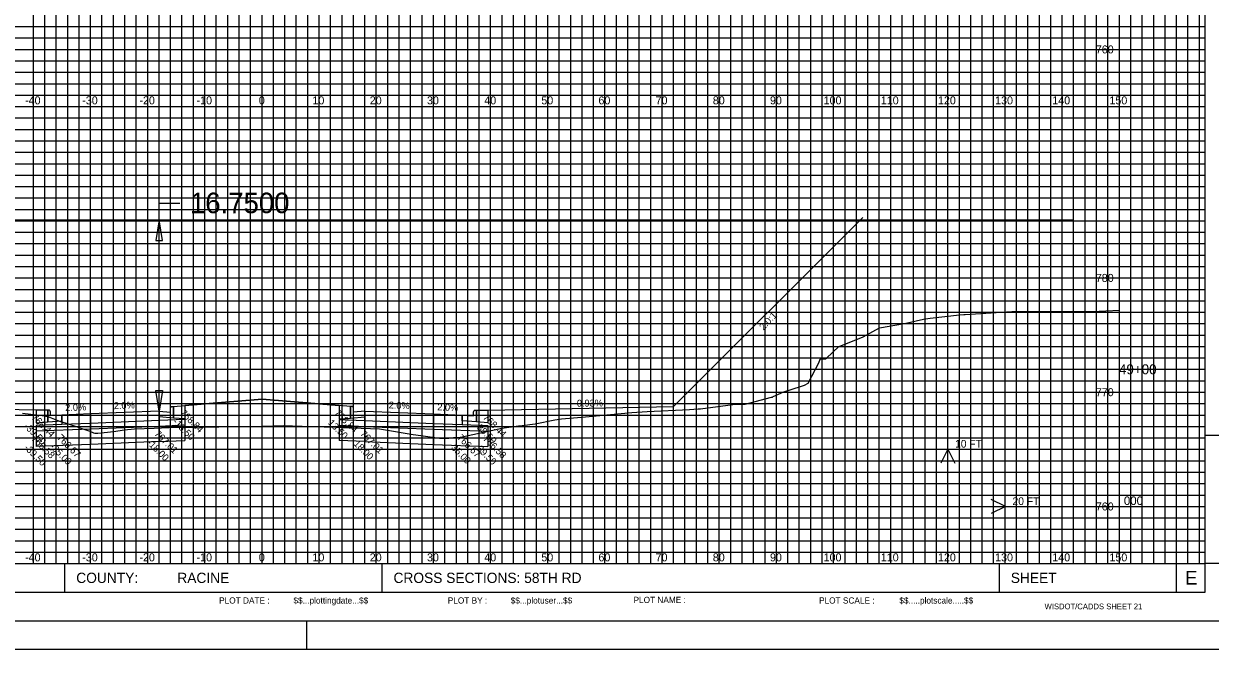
# Model space of a CAD drawing. Extents: x 578243 to 601557, y 174899 to 175559.
# Drawn here: x 600658.2 to 600865.7, y 175338.8 to 175448.3 of the extents above; entities that cross this region are included whole.
import ezdxf

# ---------------------------------------------------------------- set-up
doc = ezdxf.new("R2010")
doc.units = 0
for name, color, linetype in [('E_PROF_Grid', 7, 'Continuous'), ('E_PROF_GridMin', 7, 'Continuous'), ('P_CRDR_Label', 7, 'Continuous'), ('P_CRDR_Link', 7, 'Continuous'), ('P_E_XS_Ground', 7, 'Continuous'), ('P_RW_SlopeIntercepts', 7, 'Continuous'), ('P_XS_Text', 7, 'Continuous'), ('PLT_Sheet_Border', 7, 'Continuous'), ('PLT_Sheet_Info', 7, 'Continuous')]:
    doc.layers.add(name, color=color, linetype=linetype)

msp = doc.modelspace()

# ---------------------------------------------------------------- linework, layer by layer
at = {"layer": 'E_PROF_Grid'}
for p, q in [((600659.84, 175353.8), (600659.84, 175548.8)), ((600669.84, 175353.8), (600669.84, 175548.8)), ((600679.84, 175353.8), (600679.84, 175548.8)), ((600689.84, 175353.8), (600689.84, 175548.8)), ((600699.84, 175353.8), (600699.84, 175548.8)), ((600709.84, 175353.8), (600709.84, 175548.8)), ((600719.84, 175353.8), (600719.84, 175548.8)), ((600729.84, 175353.8), (600729.84, 175548.8)), ((600739.84, 175353.8), (600739.84, 175548.8)), ((600749.84, 175353.8), (600749.84, 175548.8)), ((600759.84, 175353.8), (600759.84, 175548.8)), ((600769.84, 175353.8), (600769.84, 175548.8)), ((600779.84, 175353.8), (600779.84, 175548.8)), ((600789.84, 175353.8), (600789.84, 175548.8)), ((600799.84, 175353.8), (600799.84, 175548.8)), ((600809.84, 175353.8), (600809.84, 175548.8)), ((600819.84, 175353.8), (600819.84, 175548.8)), ((600829.84, 175353.8), (600829.84, 175548.8)), ((600839.84, 175353.8), (600839.84, 175548.8)), ((600849.84, 175353.8), (600849.84, 175548.8)), ((600859.84, 175353.8), (600859.84, 175548.8)), ((600549.84, 175443.8), (600864.84, 175443.8)), ((600549.84, 175433.8), (600864.84, 175433.8)), ((600549.84, 175423.8), (600864.84, 175423.8)), ((600549.84, 175413.8), (600864.84, 175413.8)), ((600549.84, 175403.8), (600864.84, 175403.8)), ((600549.84, 175393.8), (600864.84, 175393.8)), ((600549.84, 175383.8), (600864.84, 175383.8)), ((600549.84, 175373.8), (600864.84, 175373.8)), ((600549.84, 175363.8), (600864.84, 175363.8))]:
    msp.add_line(p, q, dxfattribs=at)
at = {"layer": 'E_PROF_GridMin'}
for p, q in [((600661.84, 175353.8), (600661.84, 175548.8)), ((600663.84, 175353.8), (600663.84, 175548.8)), ((600665.84, 175353.8), (600665.84, 175548.8)), ((600667.84, 175353.8), (600667.84, 175548.8)), ((600671.84, 175353.8), (600671.84, 175548.8)), ((600673.84, 175353.8), (600673.84, 175548.8)), ((600675.84, 175353.8), (600675.84, 175548.8)), ((600677.84, 175353.8), (600677.84, 175548.8)), ((600681.84, 175353.8), (600681.84, 175548.8)), ((600683.84, 175353.8), (600683.84, 175548.8)), ((600685.84, 175353.8), (600685.84, 175548.8)), ((600687.84, 175353.8), (600687.84, 175548.8)), ((600691.84, 175353.8), (600691.84, 175548.8)), ((600693.84, 175353.8), (600693.84, 175548.8)), ((600695.84, 175353.8), (600695.84, 175548.8)), ((600697.84, 175353.8), (600697.84, 175548.8)), ((600701.84, 175353.8), (600701.84, 175548.8)), ((600703.84, 175353.8), (600703.84, 175548.8)), ((600705.84, 175353.8), (600705.84, 175548.8)), ((600707.84, 175353.8), (600707.84, 175548.8)), ((600711.84, 175353.8), (600711.84, 175548.8)), ((600713.84, 175353.8), (600713.84, 175548.8)), ((600715.84, 175353.8), (600715.84, 175548.8)), ((600717.84, 175353.8), (600717.84, 175548.8)), ((600721.84, 175353.8), (600721.84, 175548.8)), ((600723.84, 175353.8), (600723.84, 175548.8)), ((600725.84, 175353.8), (600725.84, 175548.8)), ((600727.84, 175353.8), (600727.84, 175548.8)), ((600731.84, 175353.8), (600731.84, 175548.8)), ((600733.84, 175353.8), (600733.84, 175548.8)), ((600735.84, 175353.8), (600735.84, 175548.8)), ((600737.84, 175353.8), (600737.84, 175548.8)), ((600741.84, 175353.8), (600741.84, 175548.8)), ((600743.84, 175353.8), (600743.84, 175548.8)), ((600745.84, 175353.8), (600745.84, 175548.8)), ((600747.84, 175353.8), (600747.84, 175548.8)), ((600751.84, 175353.8), (600751.84, 175548.8)), ((600753.84, 175353.8), (600753.84, 175548.8)), ((600755.84, 175353.8), (600755.84, 175548.8)), ((600757.84, 175353.8), (600757.84, 175548.8)), ((600761.84, 175353.8), (600761.84, 175548.8)), ((600763.84, 175353.8), (600763.84, 175548.8)), ((600765.84, 175353.8), (600765.84, 175548.8)), ((600767.84, 175353.8), (600767.84, 175548.8)), ((600771.84, 175353.8), (600771.84, 175548.8)), ((600773.84, 175353.8), (600773.84, 175548.8)), ((600775.84, 175353.8), (600775.84, 175548.8)), ((600777.84, 175353.8), (600777.84, 175548.8)), ((600781.84, 175353.8), (600781.84, 175548.8)), ((600783.84, 175353.8), (600783.84, 175548.8)), ((600785.84, 175353.8), (600785.84, 175548.8)), ((600787.84, 175353.8), (600787.84, 175548.8)), ((600791.84, 175353.8), (600791.84, 175548.8)), ((600793.84, 175353.8), (600793.84, 175548.8)), ((600795.84, 175353.8), (600795.84, 175548.8)), ((600797.84, 175353.8), (600797.84, 175548.8)), ((600801.84, 175353.8), (600801.84, 175548.8)), ((600803.84, 175353.8), (600803.84, 175548.8)), ((600805.84, 175353.8), (600805.84, 175548.8)), ((600807.84, 175353.8), (600807.84, 175548.8)), ((600811.84, 175353.8), (600811.84, 175548.8)), ((600813.84, 175353.8), (600813.84, 175548.8)), ((600815.84, 175353.8), (600815.84, 175548.8)), ((600817.84, 175353.8), (600817.84, 175548.8)), ((600821.84, 175353.8), (600821.84, 175548.8)), ((600823.84, 175353.8), (600823.84, 175548.8)), ((600825.84, 175353.8), (600825.84, 175548.8)), ((600827.84, 175353.8), (600827.84, 175548.8)), ((600831.84, 175353.8), (600831.84, 175548.8)), ((600833.84, 175353.8), (600833.84, 175548.8)), ((600835.84, 175353.8), (600835.84, 175548.8)), ((600837.84, 175353.8), (600837.84, 175548.8)), ((600841.84, 175353.8), (600841.84, 175548.8)), ((600843.84, 175353.8), (600843.84, 175548.8)), ((600845.84, 175353.8), (600845.84, 175548.8)), ((600847.84, 175353.8), (600847.84, 175548.8)), ((600851.84, 175353.8), (600851.84, 175548.8)), ((600853.84, 175353.8), (600853.84, 175548.8)), ((600855.84, 175353.8), (600855.84, 175548.8)), ((600857.84, 175353.8), (600857.84, 175548.8)), ((600861.84, 175353.8), (600861.84, 175548.8)), ((600863.84, 175353.8), (600863.84, 175548.8)), ((600549.84, 175447.8), (600864.84, 175447.8)), ((600549.84, 175445.8), (600864.84, 175445.8)), ((600549.84, 175441.8), (600864.84, 175441.8)), ((600549.84, 175439.8), (600864.84, 175439.8)), ((600549.84, 175437.8), (600864.84, 175437.8)), ((600549.84, 175435.8), (600864.84, 175435.8)), ((600549.84, 175431.8), (600864.84, 175431.8)), ((600549.84, 175429.8), (600864.84, 175429.8)), ((600549.84, 175427.8), (600864.84, 175427.8)), ((600549.84, 175425.8), (600864.84, 175425.8)), ((600549.84, 175421.8), (600864.84, 175421.8)), ((600549.84, 175419.8), (600864.84, 175419.8)), ((600549.84, 175417.8), (600864.84, 175417.8)), ((600549.84, 175415.8), (600864.84, 175415.8)), ((600549.84, 175411.8), (600864.84, 175411.8)), ((600549.84, 175409.8), (600864.84, 175409.8)), ((600549.84, 175407.8), (600864.84, 175407.8)), ((600549.84, 175405.8), (600864.84, 175405.8)), ((600549.84, 175401.8), (600864.84, 175401.8)), ((600549.84, 175399.8), (600864.84, 175399.8)), ((600549.84, 175397.8), (600864.84, 175397.8)), ((600549.84, 175395.8), (600864.84, 175395.8)), ((600549.84, 175391.8), (600864.84, 175391.8)), ((600549.84, 175389.8), (600864.84, 175389.8)), ((600549.84, 175387.8), (600864.84, 175387.8)), ((600549.84, 175385.8), (600864.84, 175385.8)), ((600549.84, 175381.8), (600864.84, 175381.8)), ((600549.84, 175379.8), (600864.84, 175379.8)), ((600549.84, 175377.8), (600864.84, 175377.8)), ((600549.84, 175375.8), (600864.84, 175375.8)), ((600549.84, 175371.8), (600864.84, 175371.8)), ((600549.84, 175369.8), (600864.84, 175369.8)), ((600549.84, 175367.8), (600864.84, 175367.8)), ((600549.84, 175365.8), (600864.84, 175365.8)), ((600549.84, 175361.8), (600864.84, 175361.8)), ((600549.84, 175359.8), (600864.84, 175359.8)), ((600549.84, 175357.8), (600864.84, 175357.8)), ((600549.84, 175355.8), (600864.84, 175355.8))]:
    msp.add_line(p, q, dxfattribs=at)
at = {"layer": 'P_CRDR_Link'}
msp.add_line((600804.95, 175414.4), (600771.84, 175381.28), dxfattribs=at)
for points in [[(600686.34, 175381.48), (600699.84, 175382.56)], [(600686.34, 175381.48), (600699.84, 175382.56)], [(600699.84, 175382.56), (600686.34, 175381.48)], [(600699.84, 175382.56), (600713.34, 175381.48)], [(600699.84, 175382.56), (600713.34, 175381.48)], [(600713.34, 175381.48), (600699.84, 175382.56)], [(600660.34, 175380.68), (600627.84, 175381.28)], [(600660.34, 175380.68), (600627.84, 175381.28)], [(600662.34, 175380.64), (600660.34, 175380.68)], [(600660.34, 175380.68), (600660.34, 175378.44)], [(600660.34, 175380.68), (600660.34, 175378.44)], [(600660.34, 175380.68), (600660.34, 175378.44)], [(600662.66, 175380.64), (600662.34, 175380.64)], [(600662.66, 175380.64), (600662.34, 175380.64)], [(600662.34, 175380.64), (600662.34, 175378.6)], [(600662.34, 175378.6), (600662.34, 175380.64)], [(600662.74, 175380.6), (600662.66, 175380.64)], [(600662.74, 175380.6), (600662.66, 175380.64)], [(600662.8, 175380.48), (600662.74, 175380.6)], [(600662.8, 175380.48), (600662.74, 175380.6)], [(600662.82, 175380.32), (600662.8, 175380.48)], [(600662.82, 175380.32), (600662.8, 175380.48)], [(600662.84, 175379.64), (600662.82, 175380.32)], [(600662.84, 175379.64), (600662.82, 175380.32)], [(600681.84, 175380.48), (600669.84, 175380)], [(600681.84, 175380.48), (600681.84, 175378.82)], [(600681.84, 175380.48), (600681.84, 175378.82)], [(600681.84, 175380.48), (600681.84, 175378.82)], [(600681.84, 175380.48), (600683.84, 175380.32)], [(600681.84, 175380.48), (600683.84, 175380.32)], [(600681.84, 175379.48), (600681.84, 175380.48)], [(600683.84, 175380.32), (600683.85, 175381)], [(600683.84, 175380.32), (600683.85, 175381)], [(600683.85, 175381), (600683.88, 175381.16)], [(600683.85, 175381), (600683.88, 175381.16)], [(600683.88, 175381.16), (600683.94, 175381.28)], [(600683.88, 175381.16), (600683.94, 175381.28)], [(600683.94, 175381.28), (600684.02, 175381.32)], [(600683.94, 175381.28), (600684.02, 175381.32)], [(600684.02, 175381.32), (600684.34, 175381.32)], [(600684.02, 175381.32), (600684.34, 175381.32)], [(600684.34, 175381.32), (600686.34, 175381.48)], [(600684.34, 175381.32), (600684.34, 175379.28)], [(600684.34, 175379.28), (600684.34, 175381.32)], [(600686.34, 175381.48), (600686.34, 175379.12)], [(600686.34, 175381.48), (600686.34, 175379.12)], [(600686.34, 175381.48), (600686.34, 175379.12)], [(600686.34, 175381.48), (600686.34, 175381.48)], [(600686.34, 175381.48), (600686.34, 175381.48)], [(600686.34, 175381.48), (600686.34, 175381.48)], [(600715.34, 175381.32), (600713.34, 175381.48)], [(600713.34, 175381.48), (600713.34, 175379.12)], [(600713.34, 175381.48), (600713.34, 175379.12)], [(600713.34, 175381.48), (600713.34, 175379.12)], [(600713.34, 175381.48), (600713.34, 175381.48)], [(600713.34, 175381.48), (600713.34, 175381.48)], [(600713.34, 175381.48), (600713.34, 175381.48)], [(600715.66, 175381.32), (600715.34, 175381.32)], [(600715.66, 175381.32), (600715.34, 175381.32)], [(600715.34, 175381.32), (600715.34, 175379.28)], [(600715.34, 175379.28), (600715.34, 175381.32)], [(600715.74, 175381.28), (600715.66, 175381.32)], [(600715.74, 175381.28), (600715.66, 175381.32)], [(600715.8, 175381.16), (600715.74, 175381.28)], [(600715.8, 175381.16), (600715.74, 175381.28)], [(600715.82, 175381), (600715.8, 175381.16)], [(600715.82, 175381), (600715.8, 175381.16)], [(600715.84, 175380.32), (600715.82, 175381)], [(600715.84, 175380.32), (600715.82, 175381)], [(600717.84, 175380.48), (600715.84, 175380.32)], [(600717.84, 175380.48), (600715.84, 175380.32)], [(600717.84, 175380.48), (600729.84, 175380)], [(600717.84, 175380.48), (600717.84, 175378.82)], [(600717.84, 175380.48), (600717.84, 175378.82)], [(600717.84, 175380.48), (600717.84, 175378.82)], [(600717.84, 175379.48), (600717.84, 175380.48)], [(600736.84, 175379.64), (600736.85, 175380.32)], [(600736.84, 175379.64), (600736.85, 175380.32)], [(600736.85, 175380.32), (600736.88, 175380.48)], [(600736.85, 175380.32), (600736.88, 175380.48)], [(600736.88, 175380.48), (600736.94, 175380.6)], [(600736.88, 175380.48), (600736.94, 175380.6)], [(600736.94, 175380.6), (600737.02, 175380.64)], [(600736.94, 175380.6), (600737.02, 175380.64)], [(600737.02, 175380.64), (600737.34, 175380.64)], [(600737.02, 175380.64), (600737.34, 175380.64)], [(600737.34, 175380.64), (600739.34, 175380.68)], [(600737.34, 175380.64), (600737.34, 175378.6)], [(600737.34, 175378.6), (600737.34, 175380.64)], [(600739.34, 175380.68), (600771.84, 175381.28)], [(600739.34, 175380.68), (600771.84, 175381.28)], [(600739.34, 175380.68), (600739.34, 175378.44)], [(600739.34, 175380.68), (600739.34, 175378.44)], [(600739.34, 175380.68), (600739.34, 175378.44)], [(600660.34, 175378.44), (600662.34, 175378.6)], [(600664.84, 175378.14), (600660.34, 175377.96)], [(600660.34, 175377.96), (600660.34, 175376.96)], [(600662.34, 175378.6), (600664.84, 175378.8)], [(600662.34, 175378.6), (600664.84, 175378.8)], [(600664.84, 175379.8), (600662.84, 175379.64)], [(600664.84, 175379.8), (600662.84, 175379.64)], [(600669.84, 175380), (600664.84, 175379.8)], [(600664.84, 175379.8), (600664.84, 175378.14)], [(600664.84, 175378.8), (600664.84, 175379.8)], [(600669.84, 175378.34), (600664.84, 175378.14)], [(600669.84, 175380), (600669.84, 175378.34)], [(600669.84, 175380), (600669.84, 175378.34)], [(600681.84, 175378.82), (600669.84, 175378.34)], [(600669.84, 175378.34), (600669.84, 175377.34)], [(600669.84, 175378.34), (600669.84, 175377.34)], [(600684.34, 175379.28), (600681.84, 175379.48)], [(600684.34, 175379.28), (600681.84, 175379.48)], [(600686.34, 175379), (600681.84, 175378.82)], [(600681.84, 175378.82), (600681.84, 175377.82)], [(600681.84, 175378.82), (600681.84, 175377.82)], [(600681.84, 175378.82), (600681.84, 175377.82)], [(600686.34, 175378), (600681.84, 175377.82)], [(600686.34, 175379.12), (600684.34, 175379.28)], [(600686.34, 175379), (600686.34, 175378)], [(600686.34, 175378), (600686.34, 175375.33)], [(600713.34, 175379.12), (600715.34, 175379.28)], [(600713.34, 175379), (600717.84, 175378.82)], [(600713.34, 175379), (600713.34, 175378)], [(600713.34, 175378), (600717.84, 175377.82)], [(600713.34, 175378), (600713.34, 175375.33)], [(600715.34, 175379.28), (600717.84, 175379.48)], [(600715.34, 175379.28), (600717.84, 175379.48)], [(600717.84, 175378.82), (600729.84, 175378.34)], [(600717.84, 175378.82), (600717.84, 175377.82)], [(600717.84, 175378.82), (600717.84, 175377.82)], [(600717.84, 175378.82), (600717.84, 175377.82)], [(600729.84, 175380), (600729.84, 175378.34)], [(600729.84, 175380), (600734.84, 175379.8)], [(600729.84, 175380), (600729.84, 175378.34)], [(600729.84, 175378.34), (600729.84, 175377.34)], [(600729.84, 175378.34), (600734.84, 175378.14)], [(600729.84, 175378.34), (600729.84, 175377.34)], [(600734.84, 175379.8), (600734.84, 175378.14)], [(600734.84, 175379.8), (600736.84, 175379.64)], [(600734.84, 175379.8), (600736.84, 175379.64)], [(600734.84, 175378.8), (600734.84, 175379.8)], [(600737.34, 175378.6), (600734.84, 175378.8)], [(600737.34, 175378.6), (600734.84, 175378.8)], [(600734.84, 175378.14), (600739.34, 175377.96)], [(600739.34, 175378.44), (600737.34, 175378.6)], [(600739.34, 175377.96), (600739.34, 175376.96)], [(600669.84, 175377.34), (600660.34, 175376.96)], [(600660.34, 175376.96), (600660.34, 175374.29)], [(600681.84, 175377.82), (600669.84, 175377.34)], [(600669.84, 175377.34), (600669.84, 175374.67)], [(600669.84, 175377.34), (600669.84, 175374.67)], [(600681.84, 175377.82), (600681.84, 175375.15)], [(600681.84, 175377.82), (600681.84, 175375.15)], [(600681.84, 175377.82), (600681.84, 175375.15)], [(600717.84, 175377.82), (600729.84, 175377.34)], [(600717.84, 175377.82), (600717.84, 175375.15)], [(600717.84, 175377.82), (600717.84, 175375.15)], [(600717.84, 175377.82), (600717.84, 175375.15)], [(600729.84, 175377.34), (600729.84, 175374.67)], [(600729.84, 175377.34), (600739.34, 175376.96)], [(600729.84, 175377.34), (600729.84, 175374.67)], [(600739.34, 175376.96), (600739.34, 175374.29)], [(600669.84, 175374.67), (600660.34, 175374.29)], [(600681.84, 175375.15), (600669.84, 175374.67)], [(600681.84, 175375.15), (600686.34, 175375.33)], [(600717.84, 175375.15), (600713.34, 175375.33)], [(600717.84, 175375.15), (600729.84, 175374.67)], [(600729.84, 175374.67), (600739.34, 175374.29)]]:
    msp.add_lwpolyline(points, dxfattribs=at)
at = {"layer": 'P_E_XS_Ground'}
msp.add_lwpolyline([(600657.92, 175380.12), (600661.4, 175379.69), (600662.39, 175379.53), (600664.4, 175378.71), (600665.6, 175378.37), (600669.71, 175376.96), (600670.34, 175376.71), (600670.61, 175376.6), (600670.61, 175376.6), (600671.11, 175376.65), (600673.92, 175376.91), (600675.7, 175377.19), (600677.53, 175377.38), (600680.96, 175377.53), (600683.56, 175377.64), (600688.48, 175377.69), (600699.84, 175377.88), (600703.56, 175377.94), (600706.85, 175377.83), (600710.7, 175377.73), (600712.9, 175377.68), (600712.9, 175377.69), (600713.85, 175377.61), (600715.64, 175377.58), (600720.38, 175377.4), (600721.1, 175377.27), (600726.26, 175376.42), (600727.63, 175376.24), (600730.51, 175375.83), (600730.92, 175375.78), (600732.39, 175375.74), (600732.51, 175375.75), (600733.35, 175375.84), (600734.52, 175375.95), (600734.87, 175375.98), (600741.81, 175377.51), (600744.71, 175377.9), (600745.33, 175377.98), (600747.63, 175378.28), (600751.08, 175378.98), (600752.24, 175379.11), (600756.43, 175379.46), (600764.57, 175380.23), (600767.23, 175380.4), (600774.64, 175380.76), (600776.12, 175380.87), (600776.57, 175380.91), (600782.2, 175381.63), (600784.34, 175381.7), (600788.96, 175382.9), (600789.16, 175382.94), (600789.29, 175383.02), (600791.15, 175383.87), (600794.22, 175384.87), (600794.77, 175385.05), (600795.37, 175385.37), (600797.23, 175388.95), (600797.5, 175389.57), (600797.65, 175389.63), (600798.45, 175389.61), (600798.62, 175389.76), (600800.75, 175391.81), (600801.42, 175392.01), (600805.03, 175393.51), (600807.88, 175395.06), (600812.27, 175395.82), (600815.55, 175396.56), (600816.75, 175396.74), (600821.89, 175397.32), (600822.64, 175397.42), (600822.85, 175397.42), (600831.04, 175397.9), (600832.78, 175397.9), (600839.33, 175397.92), (600840.68, 175397.9), (600845.05, 175397.93), (600849.84, 175398.18)], dxfattribs=at)
at = {"layer": 'P_RW_SlopeIntercepts'}
for p, q in [((600681.84, 175416.91), (600685.44, 175416.91)), ((600681.84, 175380.48), (600681.84, 175416.91)), ((600581.84, 175413.98), (600841.84, 175413.98))]:
    msp.add_line(p, q, dxfattribs=at)
for points in [[(600681.24, 175410.38), (600682.44, 175410.38), (600681.84, 175413.98)], [(600681.24, 175384.08), (600682.44, 175384.08), (600681.84, 175380.48)]]:
    msp.add_lwpolyline(points, close=True, dxfattribs=at)
at = {"layer": 'PLT_Sheet_Border'}
for points in [[(600537.19, 175338.8), (600877.19, 175338.8), (600877.19, 175558.8), (600537.19, 175558.8)], [(600539.59, 175343.8), (600870.59, 175343.8), (600870.59, 175553.8), (600539.59, 175553.8)]]:
    msp.add_lwpolyline(points, close=True, dxfattribs=at)
at = {"layer": 'PLT_Sheet_Info'}
for p, q in [((600864.84, 175348.8), (600864.84, 175548.8)), ((600549.84, 175353.8), (600864.84, 175353.8)), ((600665.34, 175348.8), (600665.34, 175353.8)), ((600720.84, 175348.8), (600720.84, 175353.8)), ((600828.84, 175348.8), (600828.84, 175353.8)), ((600859.84, 175348.8), (600859.84, 175353.8)), ((600549.84, 175348.8), (600864.84, 175348.8)), ((600707.69, 175338.8), (600707.69, 175343.8)), ((600702.69, 175338.8), (600712.69, 175338.8))]:
    msp.add_line(p, q, dxfattribs=at)
msp.add_lwpolyline([(600864.84, 175376.3), (600870.34, 175376.3), (600870.34, 175353.8), (600864.84, 175353.8)], close=True, dxfattribs=at)
for points in [[(600819.84, 175373.84), (600818.6, 175371.36)], [(600819.84, 175363.8), (600819.84, 175373.84), (600821.08, 175371.36)], [(600819.84, 175363.8), (600829.89, 175363.8), (600827.4, 175362.55)], [(600829.89, 175363.8), (600827.4, 175365.04)]]:
    msp.add_lwpolyline(points, dxfattribs=at)

# ---------------------------------------------------------------- texts
at = {"layer": 'P_CRDR_Label'}
for s, rotation, p in [('2.0:1', 46.711, (600787.58, 175394.57)), ('2.0%', 2.2906, (600673.93, 175380.82)), ('2.0%', 357.7094, (600721.99, 175380.97)), ('0.93%', 0.4313, (600754.93, 175381.27)), ('768.44', 315, (600659.41, 175379.27)), ('2.0%', 2.2906, (600665.43, 175380.48)), ('768.84', 315, (600685.41, 175380.07)), ('768.84', 315, (600712.41, 175380.07)), ('2.0%', 357.7094, (600730.49, 175380.63)), ('768.44', 315, (600738.41, 175379.27)), ('-39.50', 315, (600658.14, 175377.7)), ('-13.50', 315, (600684.14, 175378.5)), ('13.50', 315, (600711.31, 175378.33)), ('39.50', 315, (600737.33, 175377.5)), ('766.58', 315, (600659.41, 175375.54)), ('766.67', 315, (600663.91, 175375.72)), ('767.01', 315, (600680.91, 175376.4)), ('767.01', 315, (600680.91, 175376.4)), ('767.01', 315, (600680.91, 175376.4)), ('767.01', 315, (600716.91, 175376.4)), ('767.01', 315, (600716.91, 175376.4)), ('767.01', 315, (600716.91, 175376.4)), ('766.67', 315, (600733.91, 175375.72)), ('766.58', 315, (600738.41, 175375.54)), ('-39.50', 315, (600658.13, 175373.98)), ('-35.00', 315, (600662.63, 175374.16)), ('-18.00', 315, (600679.62, 175374.85)), ('-18.00', 315, (600679.62, 175374.85)), ('-18.00', 315, (600679.62, 175374.85)), ('18.00', 315, (600715.79, 175374.68)), ('18.00', 315, (600715.79, 175374.68)), ('18.00', 315, (600715.79, 175374.68)), ('35.00', 315, (600732.82, 175373.97)), ('39.50', 315, (600737.32, 175373.79))]:
    msp.add_text(s, height=1.2, rotation=rotation, dxfattribs=at).set_placement(p)
at = {"layer": 'P_RW_SlopeIntercepts'}
msp.add_text('16.7500', height=3.6, dxfattribs=at).set_placement((600687.24, 175415.13))
at = {"layer": 'P_XS_Text'}
for s, height, p in [('760', 1.4, (600845.72, 175443.1)), ('-40', 1.4, (600658.39, 175434.18)), ('-30', 1.4, (600668.39, 175434.18)), ('-20', 1.4, (600678.39, 175434.18)), ('-10', 1.4, (600688.39, 175434.18)), ('0', 1.4, (600699.28, 175434.18)), ('0', 1.4, (600699.28, 175434.18)), ('10', 1.4, (600708.66, 175434.18)), ('20', 1.4, (600718.69, 175434.18)), ('30', 1.4, (600728.7, 175434.18)), ('40', 1.4, (600738.73, 175434.18)), ('50', 1.4, (600748.71, 175434.18)), ('60', 1.4, (600758.7, 175434.18)), ('70', 1.4, (600768.7, 175434.18)), ('80', 1.4, (600778.71, 175434.18)), ('90', 1.4, (600788.71, 175434.18)), ('100', 1.4, (600798.1, 175434.18)), ('110', 1.4, (600808.1, 175434.18)), ('120', 1.4, (600818.1, 175434.18)), ('130', 1.4, (600828.1, 175434.18)), ('140', 1.4, (600838.1, 175434.18)), ('150', 1.4, (600848.1, 175434.18)), ('780', 1.4, (600845.72, 175403.1)), ('49+00', 1.75, (600849.77, 175386.93)), ('770', 1.4, (600845.72, 175383.1)), ('760', 1.4, (600845.72, 175363.1)), ('-40', 1.4, (600658.39, 175354.19)), ('-30', 1.4, (600668.39, 175354.19)), ('-20', 1.4, (600678.39, 175354.19)), ('-10', 1.4, (600688.39, 175354.19)), ('0', 1.4, (600699.28, 175354.19)), ('0', 1.4, (600699.28, 175354.19)), ('10', 1.4, (600708.66, 175354.19)), ('20', 1.4, (600718.69, 175354.19)), ('30', 1.4, (600728.7, 175354.19)), ('40', 1.4, (600738.73, 175354.19)), ('50', 1.4, (600748.71, 175354.19)), ('60', 1.4, (600758.7, 175354.19)), ('70', 1.4, (600768.7, 175354.19)), ('80', 1.4, (600778.71, 175354.19)), ('90', 1.4, (600788.71, 175354.19)), ('100', 1.4, (600798.1, 175354.19)), ('110', 1.4, (600808.1, 175354.19)), ('120', 1.4, (600818.1, 175354.19)), ('130', 1.4, (600828.1, 175354.19)), ('140', 1.4, (600838.1, 175354.19)), ('150', 1.4, (600848.1, 175354.19))]:
    msp.add_text(s, height=height, rotation=360, dxfattribs=at).set_placement(p)
at = {"layer": 'PLT_Sheet_Info'}
for s, height, p in [('  10 FT', 1.347, (600820.09, 175374.09)), ('     000', 1.5, (600847.84, 175364.05)), ('  20 FT', 1.347, (600830.14, 175364.05)), ('COUNTY:', 1.8, (600667.34, 175350.4)), ('       RACINE       ', 1.8, (600680.34, 175350.4)), ('CROSS SECTIONS: 58TH RD                           ', 1.8, (600722.84, 175350.4)), ('SHEET ', 1.8, (600830.84, 175350.4)), ('E', 2.4, (600861.36, 175350.11)), ('PLOT NAME :                      ', 1.08, (600764.84, 175346.9)), ('PLOT SCALE : ', 1.08, (600797.3, 175346.8)), ('$$.....plotscale.....$$', 1.08, (600811.34, 175346.8)), ('WISDOT/CADDS SHEET 21', 1, (600836.76, 175345.8))]:
    msp.add_text(s, height=height, dxfattribs=at).set_placement(p)
for s, p in [('PLOT DATE :', (600692.34, 175346.8)), ('$$...plottingdate...$$', (600705.34, 175346.8)), ('PLOT BY :', (600732.34, 175346.8)), ('$$...plotuser...$$', (600743.34, 175346.8))]:
    msp.add_text(s, height=1.08, rotation=360, dxfattribs=at).set_placement(p)

doc.saveas('drawing.dxf')
